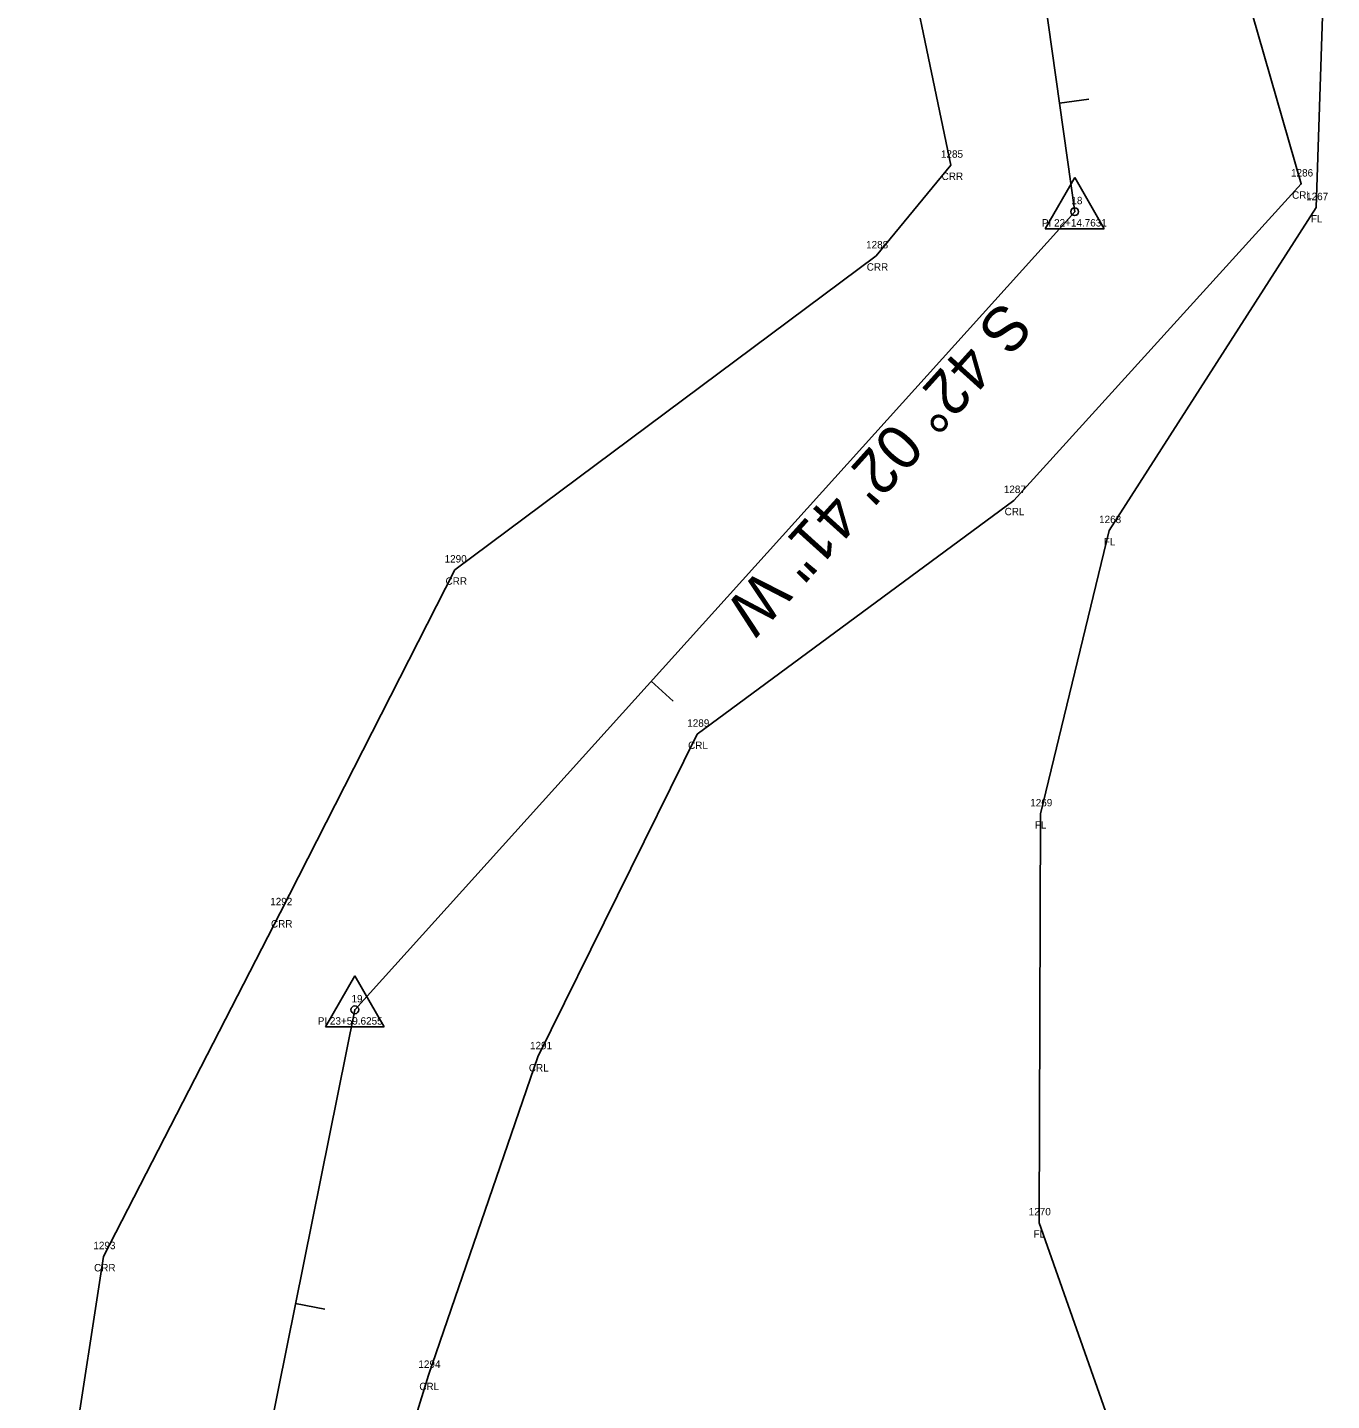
# Model space of a CAD drawing. Extents: x 1964982 to 1970527, y 1116335 to 1119906.
# Drawn here: x 1967789.9 to 1967965.7, y 1118027.3 to 1118212.4 of the extents above; entities that cross this region are included whole.
import ezdxf

# ---------------------------------------------------------------- set-up
doc = ezdxf.new("R2010")
doc.units = 0
for name, color, linetype in [('RD_EX_DV_Prop', 7, 'Continuous'), ('RD_EX_Fence_Other', 7, 'Continuous'), ('RD_EX_Fence_Other_txCode', 7, 'Continuous'), ('RD_EX_H2O', 7, 'Continuous'), ('RD_EX_H2O_txCode', 7, 'Continuous'), ('RD_HC_CL', 7, 'Continuous'), ('RD_HC_Data', 7, 'Continuous'), ('RD_HC_Data_Tic', 7, 'Continuous'), ('RD_HC_txCode', 7, 'Continuous'), ('RD_SMD_Locator', 7, 'Continuous')]:
    doc.layers.add(name, color=color, linetype=linetype)

msp = doc.modelspace()

# ---------------------------------------------------------------- linework, layer by layer
at = {"layer": 'RD_EX_DV_Prop'}
for p, q in [((1967911.37, 1118327.66), (1967931.05, 1118187.54)), ((1967931.05, 1118187.54), (1967834.04, 1118079.96)), ((1967834.04, 1118079.96), (1967804.81, 1117934.87))]:
    msp.add_line(p, q, dxfattribs=at)
at = {"layer": 'RD_EX_Fence_Other'}
msp.add_lwpolyline([(1967920.92, 1118368.66), (1967937.87, 1118342.4), (1967954.81, 1118301.31), (1967965.67, 1118250.56), (1967963.61, 1118188.09), (1967935.71, 1118144.56), (1967926.43, 1118106.38), (1967926.25, 1118051.25), (1967941.61, 1118007.63), (1967945.93, 1117995.37)], dxfattribs=at)
at = {"layer": 'RD_EX_H2O'}
for points in [[(1967852.4, 1118390.04), (1967912.21, 1118383.64), (1967925.08, 1118336.82), (1967944.14, 1118294.4), (1967946.67, 1118243.15), (1967961.58, 1118191.28), (1967922.84, 1118148.62), (1967880.18, 1118117.11), (1967858.72, 1118073.64), (1967843.96, 1118030.69), (1967829.77, 1117984.65), (1967829.63, 1117934.73), (1967834.65, 1117903.36)], [(1967848.54, 1118347.45), (1967880.38, 1118337.78), (1967886.93, 1118331.58), (1967896.4, 1118282.85), (1967906.33, 1118232.39), (1967914.38, 1118193.81), (1967904.29, 1118181.59), (1967847.52, 1118139.25), (1967823.99, 1118093.05), (1967800.15, 1118046.69), (1967791.83, 1117992.41), (1967789.93, 1117935.61), (1967798.32, 1117889.19), (1967796.67, 1117880.97)]]:
    msp.add_lwpolyline(points, dxfattribs=at)
at = {"layer": 'RD_HC_CL'}
for p, q in [((1967911.37, 1118327.66), (1967931.05, 1118187.54)), ((1967931.05, 1118187.54), (1967834.04, 1118079.96)), ((1967834.04, 1118079.96), (1967804.81, 1117934.87))]:
    msp.add_line(p, q, dxfattribs=at)
at = {"layer": 'RD_HC_Data'}
for p, q in [((1967927.08, 1118185.25), (1967931.06, 1118192.13)), ((1967931.06, 1118192.13), (1967935.02, 1118185.25)), ((1967927.08, 1118185.25), (1967935.02, 1118185.25)), ((1967830.07, 1118077.67), (1967834.04, 1118084.55)), ((1967834.04, 1118084.55), (1967838.01, 1118077.67)), ((1967830.07, 1118077.67), (1967838.01, 1118077.67))]:
    msp.add_line(p, q, dxfattribs=at)
for centre in [(1967931.05, 1118187.54), (1967834.04, 1118079.96)]:
    msp.add_circle(centre, 0.529, dxfattribs=at)
at = {"layer": 'RD_HC_Data_Tic'}
for p, q in [((1967929, 1118202.16), (1967932.96, 1118202.72)), ((1967873.97, 1118124.24), (1967876.94, 1118121.56)), ((1967826.06, 1118040.38), (1967829.99, 1118039.59))]:
    msp.add_line(p, q, dxfattribs=at)
at = {"layer": 'RD_SMD_Locator'}
for centre in [(1967914.38, 1118193.81), (1967961.58, 1118191.28), (1967931.05, 1118187.54), (1967963.61, 1118188.09), (1967904.29, 1118181.59), (1967922.84, 1118148.62), (1967935.71, 1118144.56), (1967847.52, 1118139.25), (1967880.18, 1118117.11), (1967926.43, 1118106.38), (1967823.99, 1118093.05), (1967834.04, 1118079.96), (1967858.72, 1118073.64), (1967926.25, 1118051.25), (1967800.15, 1118046.69), (1967843.96, 1118030.69)]:
    msp.add_circle(centre, 0.001, dxfattribs=at)

# ---------------------------------------------------------------- texts
at = {"layer": 'RD_EX_Fence_Other_txCode'}
for s, p in [('1267', (1967962.24, 1118189.09)), ('FL', (1967962.88, 1118186.09)), ('1268', (1967934.34, 1118145.56)), ('FL', (1967934.98, 1118142.56)), ('1269', (1967925.06, 1118107.38)), ('FL', (1967925.69, 1118104.38)), ('1270', (1967924.86, 1118052.25)), ('FL', (1967925.51, 1118049.25))]:
    msp.add_text(s, height=1, dxfattribs=at).set_placement(p)
at = {"layer": 'RD_EX_H2O_txCode'}
for s, p in [('1285', (1967913.03, 1118194.81)), ('1286', (1967960.21, 1118192.28)), ('CRR', (1967913.12, 1118191.81)), ('CRL', (1967960.35, 1118189.28)), ('1288', (1967902.94, 1118182.59)), ('CRR', (1967903.03, 1118179.59)), ('1287', (1967921.5, 1118149.62)), ('CRL', (1967921.61, 1118146.62)), ('1290', (1967846.14, 1118140.25)), ('CRR', (1967846.27, 1118137.25)), ('1289', (1967878.84, 1118118.11)), ('CRL', (1967878.95, 1118115.11)), ('1292', (1967822.64, 1118094.05)), ('CRR', (1967822.74, 1118091.05)), ('1291', (1967857.65, 1118074.64)), ('CRL', (1967857.49, 1118071.64)), ('1293', (1967798.81, 1118047.69)), ('CRR', (1967798.9, 1118044.69)), ('1294', (1967842.61, 1118031.69)), ('CRL', (1967842.73, 1118028.69))]:
    msp.add_text(s, height=1, dxfattribs=at).set_placement(p)
at = {"layer": 'RD_HC_Data'}
msp.add_text('S 42° 02\' 41" W', height=6, rotation=227.9551, dxfattribs=at).set_placement((1967921.3, 1118175.76))
at = {"layer": 'RD_HC_txCode'}
for s, p in [('18', (1967930.61, 1118188.54)), ('PI 22+14.7631', (1967926.64, 1118185.54)), ('19', (1967833.59, 1118080.96)), ('PI 23+59.6255', (1967829.05, 1118077.96))]:
    msp.add_text(s, height=1, dxfattribs=at).set_placement(p)

doc.saveas('drawing.dxf')
